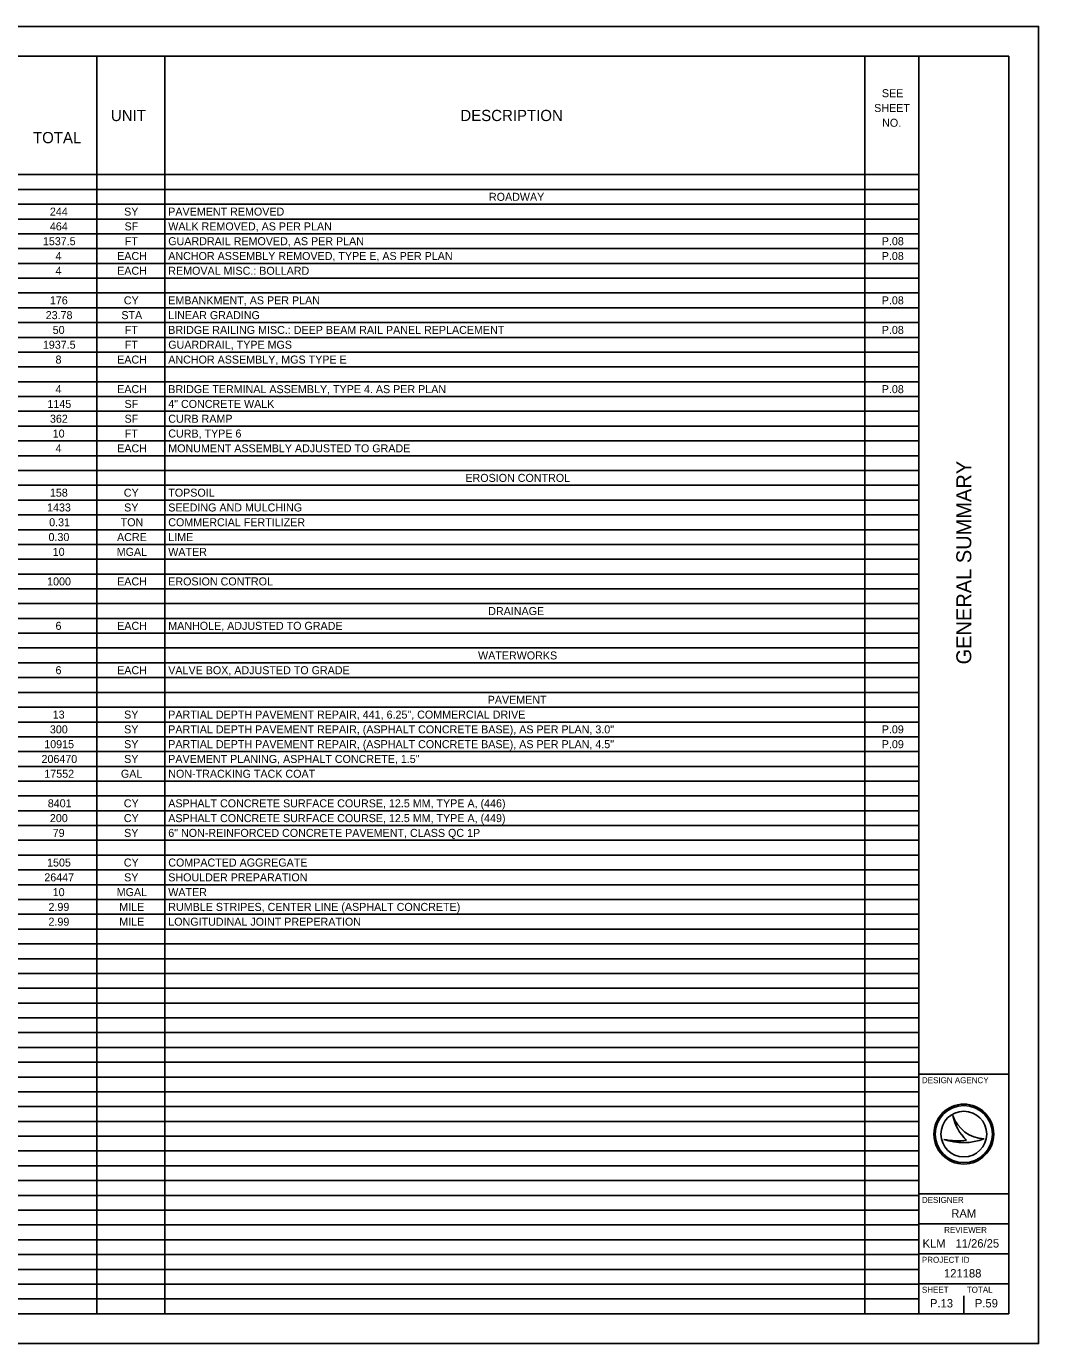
# Model space of a CAD drawing. Extents: x 0 to 34, y 0 to 22.
# Drawn here: x 17.09 to 34, y 0 to 22 of the extents above; entities that cross this region are included whole.
import ezdxf

# ---------------------------------------------------------------- set-up
doc = ezdxf.new("R2010")
doc.units = 0
for name, color, linetype in [('Default', 7, 'Continuous'), ('SH_Border', 7, 'Continuous'), ('SH_Cut_Line', 7, 'Continuous'), ('SH_Data', 7, 'Continuous')]:
    doc.layers.add(name, color=color, linetype=linetype)

msp = doc.modelspace()

# ---------------------------------------------------------------- linework, layer by layer
at = {"layer": 'Default'}
for p, q in [((1.5, 21.5), (32, 21.5)), ((18.27, 21.5), (18.27, 0.5)), ((19.404, 21.5), (19.404, 0.5)), ((31.098, 21.5), (31.098, 0.5)), ((32, 21.5), (32, 0.5)), ((1.5, 19.524), (32, 19.524)), ((1.5, 19.276), (32, 19.276)), ((1.5, 19.029), (32, 19.029)), ((1.5, 18.782), (32, 18.782)), ((1.5, 18.535), (32, 18.535)), ((1.5, 18.288), (32, 18.288)), ((1.5, 18.041), (32, 18.041)), ((1.5, 17.794), (32, 17.794)), ((1.5, 17.547), (32, 17.547)), ((1.5, 17.3), (32, 17.3)), ((1.5, 17.053), (32, 17.053)), ((1.5, 16.806), (32, 16.806)), ((1.5, 16.559), (32, 16.559)), ((1.5, 16.312), (32, 16.312)), ((1.5, 16.065), (32, 16.065)), ((1.5, 15.818), (32, 15.818)), ((1.5, 15.571), (32, 15.571)), ((1.5, 15.324), (32, 15.324)), ((1.5, 15.076), (32, 15.076)), ((1.5, 14.829), (32, 14.829)), ((1.5, 14.582), (32, 14.582)), ((1.5, 14.335), (32, 14.335)), ((1.5, 14.088), (32, 14.088)), ((1.5, 13.841), (32, 13.841)), ((1.5, 13.594), (32, 13.594)), ((1.5, 13.347), (32, 13.347)), ((1.5, 13.1), (32, 13.1)), ((1.5, 12.853), (32, 12.853)), ((1.5, 12.606), (32, 12.606)), ((1.5, 12.359), (32, 12.359)), ((1.5, 12.112), (32, 12.112)), ((1.5, 11.865), (32, 11.865)), ((1.5, 11.618), (32, 11.618)), ((1.5, 11.371), (32, 11.371)), ((1.5, 11.124), (32, 11.124)), ((1.5, 10.876), (32, 10.876)), ((1.5, 10.629), (32, 10.629)), ((1.5, 10.382), (32, 10.382)), ((1.5, 10.135), (32, 10.135)), ((1.5, 9.888), (32, 9.888)), ((1.5, 9.641), (32, 9.641)), ((1.5, 9.394), (32, 9.394)), ((1.5, 9.147), (32, 9.147)), ((1.5, 8.9), (32, 8.9)), ((1.5, 8.653), (32, 8.653)), ((1.5, 8.406), (32, 8.406)), ((1.5, 8.159), (32, 8.159)), ((1.5, 7.912), (32, 7.912)), ((1.5, 7.665), (32, 7.665)), ((1.5, 7.418), (32, 7.418)), ((1.5, 7.171), (32, 7.171)), ((1.5, 6.924), (32, 6.924)), ((1.5, 6.676), (32, 6.676)), ((1.5, 6.429), (32, 6.429)), ((1.5, 6.182), (32, 6.182)), ((1.5, 5.935), (32, 5.935)), ((1.5, 5.688), (32, 5.688)), ((1.5, 5.441), (32, 5.441)), ((1.5, 5.194), (32, 5.194)), ((1.5, 4.947), (32, 4.947)), ((1.5, 4.7), (32, 4.7)), ((1.5, 4.453), (32, 4.453)), ((1.5, 4.206), (32, 4.206)), ((1.5, 3.959), (32, 3.959)), ((1.5, 3.712), (32, 3.712)), ((1.5, 3.465), (32, 3.465)), ((1.5, 3.218), (32, 3.218)), ((1.5, 2.971), (32, 2.971)), ((1.5, 2.724), (32, 2.724)), ((1.5, 2.476), (32, 2.476)), ((1.5, 2.229), (32, 2.229)), ((1.5, 1.982), (32, 1.982)), ((1.5, 1.735), (32, 1.735)), ((1.5, 1.488), (32, 1.488)), ((1.5, 1.241), (32, 1.241)), ((1.5, 0.994), (32, 0.994)), ((1.5, 0.747), (32, 0.747)), ((1.5, 0.5), (32, 0.5))]:
    msp.add_line(p, q, dxfattribs=at)
for points in [[(19.404, 12.359), (31.098, 12.359), (31.098, 12.112), (19.404, 12.112)], [(19.404, 11.618), (31.098, 11.618), (31.098, 11.371), (19.404, 11.371)], [(19.404, 10.876), (31.098, 10.876), (31.098, 10.629), (19.404, 10.629)], [(19.404, 10.629), (31.098, 10.629), (31.098, 10.382), (19.404, 10.382)], [(19.404, 10.382), (31.098, 10.382), (31.098, 10.135), (19.404, 10.135)], [(19.404, 10.135), (31.098, 10.135), (31.098, 9.888), (19.404, 9.888)]]:
    msp.add_lwpolyline(points, close=True, dxfattribs=at)
at = {"layer": 'SH_Border'}
for p, q in [((32, 0.5), (32, 21.5)), ((32, 4.5), (33.5, 4.5)), ((32, 2.5), (33.5, 2.5)), ((32, 2), (33.5, 2)), ((32, 1.5), (33.5, 1.5)), ((32, 1), (33.5, 1))]:
    msp.add_line(p, q, dxfattribs=at)
msp.add_lwpolyline([(1.5, 21.5), (33.5, 21.5), (33.5, 0.5), (1.5, 0.5)], close=True, dxfattribs=at)
at = {"layer": 'SH_Cut_Line'}
msp.add_lwpolyline([(0, 0), (34, 0), (34, 22), (0, 22)], close=True, dxfattribs=at)
at = {"layer": 'SH_Data'}
for p, q in [((32.567, 3.81), (32.567, 3.81)), ((32.417, 3.41), (32.417, 3.41)), ((32.75, 3.5), (32.75, 3.5)), ((33.087, 3.419), (33.087, 3.419)), ((32.375, 0.675), (32.375, 0.675)), ((32.75, 0.5), (32.75, 0.8))]:
    msp.add_line(p, q, dxfattribs=at)
for radius in [0.5, 0.477, 0.477, 0.382]:
    msp.add_circle((32.75, 3.5), radius, dxfattribs=at)
for centre, radius, start, end in [((33.116, 3.998), 0.58, 198.9257, 198.9319), ((33.347, 3.97), 0.796, 191.6379, 191.6421), ((33.116, 3.998), 0.58, 198.9319, 267.1657), ((33.347, 3.97), 0.796, 191.6421, 226.0947), ((32.739, 4.37), 1.013, 251.4576, 290.0832), ((32.648, 4.654), 1.266, 259.4964, 259.4995), ((32.739, 4.37), 1.013, 251.4527, 251.4576), ((32.648, 4.654), 1.266, 259.4995, 276.6672)]:
    msp.add_arc(centre, radius, start, end, dxfattribs=at)

# ---------------------------------------------------------------- texts
at = {"layer": 'Default'}
for s, height, p in [('SEE', 0.1337, (31.382, 20.817)), ('SHEET', 0.1337, (31.253, 20.57)), ('UNIT', 0.1872, (18.505, 20.418)), ('DESCRIPTION', 0.18718, (24.342, 20.418)), ('NO.', 0.1337, (31.386, 20.323)), ('TOTAL', 0.1872, (17.204, 20.048)), ('ROADWAY', 0.1337, (24.819, 19.086)), ('244', 0.1337, (17.486, 18.839)), ('SY', 0.1337, (18.726, 18.839)), ('PAVEMENT REMOVED', 0.1337, (19.463, 18.839)), ('464', 0.1337, (17.486, 18.592)), ('SF', 0.1337, (18.733, 18.592)), ('WALK REMOVED, AS PER PLAN', 0.1337, (19.463, 18.592)), ('1537.5', 0.1337, (17.369, 18.345)), ('GUARDRAIL REMOVED, AS PER PLAN', 0.1337, (19.463, 18.345)), ('P.08', 0.1337, (31.38, 18.345)), ('FT', 0.1337, (18.736, 18.345)), ('4', 0.134, (17.58, 18.098)), ('EACH', 0.1337, (18.61, 18.098)), ('ANCHOR ASSEMBLY REMOVED, TYPE E, AS PER PLAN', 0.1337, (19.463, 18.098)), ('P.08', 0.1337, (31.38, 18.098)), ('4', 0.134, (17.58, 17.851)), ('EACH', 0.1337, (18.61, 17.851)), ('REMOVAL MISC.: BOLLARD', 0.1337, (19.463, 17.851)), ('176', 0.1337, (17.486, 17.357)), ('CY', 0.1337, (18.721, 17.357)), ('EMBANKMENT, AS PER PLAN', 0.1337, (19.463, 17.357)), ('P.08', 0.1337, (31.38, 17.357)), ('23.78', 0.1337, (17.416, 17.11)), ('STA', 0.1337, (18.68, 17.11)), ('LINEAR GRADING', 0.1337, (19.463, 17.11)), ('50', 0.1337, (17.533, 16.863)), ('FT', 0.1337, (18.736, 16.863)), ('BRIDGE RAILING MISC.: DEEP BEAM RAIL PANEL REPLACEMENT', 0.1337, (19.463, 16.863)), ('P.08', 0.1337, (31.38, 16.863)), ('1937.5', 0.1337, (17.369, 16.616)), ('FT', 0.1337, (18.736, 16.616)), ('GUARDRAIL, TYPE MGS', 0.1337, (19.463, 16.616)), ('8', 0.134, (17.58, 16.368)), ('EACH', 0.1337, (18.61, 16.368)), ('ANCHOR ASSEMBLY, MGS TYPE E', 0.1337, (19.463, 16.368)), ('4', 0.134, (17.58, 15.874)), ('EACH', 0.1337, (18.61, 15.874)), ('BRIDGE TERMINAL ASSEMBLY, TYPE 4. AS PER PLAN', 0.1337, (19.463, 15.874)), ('P.08', 0.1337, (31.38, 15.874)), ('1145', 0.1337, (17.445, 15.627)), ('SF', 0.1337, (18.733, 15.627)), ('4" CONCRETE WALK', 0.1337, (19.463, 15.627)), ('362', 0.1337, (17.487, 15.38)), ('SF', 0.1337, (18.733, 15.38)), ('CURB RAMP', 0.1337, (19.463, 15.38)), ('10', 0.1337, (17.533, 15.133)), ('FT', 0.1337, (18.736, 15.133)), ('CURB, TYPE 6', 0.1337, (19.463, 15.133)), ('4', 0.134, (17.58, 14.886)), ('EACH', 0.1337, (18.61, 14.886)), ('MONUMENT ASSEMBLY ADJUSTED TO GRADE', 0.1337, (19.463, 14.886)), ('EROSION CONTROL', 0.1337, (24.426, 14.392)), ('158', 0.1337, (17.486, 14.145)), ('CY', 0.1337, (18.721, 14.145)), ('TOPSOIL', 0.1337, (19.463, 14.145)), ('1433', 0.1337, (17.439, 13.898)), ('SY', 0.1337, (18.726, 13.898)), ('SEEDING AND MULCHING', 0.1337, (19.463, 13.898)), ('0.31', 0.1337, (17.474, 13.651)), ('TON', 0.1337, (18.668, 13.651)), ('COMMERCIAL FERTILIZER', 0.1337, (19.463, 13.651)), ('0.30', 0.1337, (17.463, 13.404)), ('ACRE', 0.1337, (18.608, 13.404)), ('LIME', 0.1337, (19.463, 13.404)), ('10', 0.1337, (17.533, 13.157)), ('MGAL', 0.1337, (18.602, 13.157)), ('WATER', 0.1337, (19.463, 13.157)), ('1000', 0.1337, (17.44, 12.663)), ('EACH', 0.1337, (18.61, 12.663)), ('EROSION CONTROL', 0.1337, (19.463, 12.663)), ('DRAINAGE', 0.1337, (24.807, 12.168)), ('6', 0.134, (17.58, 11.921)), ('EACH', 0.1337, (18.61, 11.921)), ('MANHOLE, ADJUSTED TO GRADE', 0.1337, (19.463, 11.921)), ('WATERWORKS', 0.1337, (24.637, 11.427)), ('6', 0.134, (17.58, 11.18)), ('EACH', 0.1337, (18.61, 11.18)), ('VALVE BOX, ADJUSTED TO GRADE', 0.1337, (19.463, 11.18)), ('PAVEMENT', 0.1337, (24.798, 10.686)), ('13', 0.1337, (17.533, 10.439)), ('SY', 0.1337, (18.726, 10.439)), ('PARTIAL DEPTH PAVEMENT REPAIR, 441, 6.25", COMMERCIAL DRIVE', 0.1337, (19.463, 10.439)), ('300', 0.1337, (17.486, 10.192)), ('SY', 0.1337, (18.726, 10.192)), ('PARTIAL DEPTH PAVEMENT REPAIR, (ASPHALT CONCRETE BASE), AS PER PLAN, 3.0"', 0.1337, (19.463, 10.192)), ('P.09', 0.1337, (31.38, 10.192)), ('10915', 0.1337, (17.392, 9.945)), ('SY', 0.1337, (18.726, 9.945)), ('PARTIAL DEPTH PAVEMENT REPAIR, (ASPHALT CONCRETE BASE), AS PER PLAN, 4.5"', 0.1337, (19.463, 9.945)), ('P.09', 0.1337, (31.38, 9.945)), ('206470', 0.1337, (17.346, 9.698)), ('SY', 0.1337, (18.726, 9.698)), ('PAVEMENT PLANING, ASPHALT CONCRETE, 1.5"', 0.1337, (19.463, 9.698)), ('17552', 0.1337, (17.393, 9.451)), ('GAL', 0.1337, (18.672, 9.451)), ('NON-TRACKING TACK COAT', 0.1337, (19.463, 9.451)), ('8401', 0.1337, (17.451, 8.957)), ('CY', 0.1337, (18.721, 8.957)), ('ASPHALT CONCRETE SURFACE COURSE, 12.5 MM, TYPE A, (446)', 0.1337, (19.463, 8.957)), ('200', 0.1337, (17.486, 8.71)), ('CY', 0.1337, (18.721, 8.71)), ('ASPHALT CONCRETE SURFACE COURSE, 12.5 MM, TYPE A, (449)', 0.1337, (19.463, 8.71)), ('79', 0.1337, (17.533, 8.463)), ('SY', 0.1337, (18.726, 8.463)), ('6" NON-REINFORCED CONCRETE PAVEMENT, CLASS QC 1P', 0.1337, (19.463, 8.463)), ('1505', 0.1337, (17.439, 7.968)), ('CY', 0.1337, (18.721, 7.968)), ('COMPACTED AGGREGATE', 0.1337, (19.463, 7.968)), ('26447', 0.1337, (17.393, 7.721)), ('SY', 0.1337, (18.726, 7.721)), ('SHOULDER PREPARATION', 0.1337, (19.463, 7.721)), ('10', 0.1337, (17.533, 7.474)), ('MGAL', 0.1337, (18.602, 7.474)), ('WATER', 0.1337, (19.463, 7.474)), ('2.99', 0.1337, (17.463, 7.227)), ('MILE', 0.1337, (18.645, 7.227)), ('RUMBLE STRIPES, CENTER LINE (ASPHALT CONCRETE)', 0.1337, (19.463, 7.227)), ('2.99', 0.1337, (17.463, 6.98)), ('MILE', 0.1337, (18.645, 6.98)), ('LONGITUDINAL JOINT PREPERATION', 0.1337, (19.463, 6.98))]:
    msp.add_text(s, height=height, dxfattribs=at).set_placement(p)
at = {"layer": 'SH_Data'}
msp.add_text('GENERAL SUMMARY', height=0.25, rotation=90, dxfattribs=at).set_placement((32.875, 11.344))
for s, height, p in [('DESIGN AGENCY', 0.1, (32.05, 4.35)), ('DESIGNER', 0.1, (32.05, 2.35)), ('RAM', 0.14, (32.541, 2.105)), ('REVIEWER', 0.1, (32.422, 1.85)), ('KLM', 0.14, (32.061, 1.605)), ('11/26/25', 0.14, (32.611, 1.605)), ('PROJECT ID', 0.1, (32.05, 1.35)), ('121188', 0.14, (32.419, 1.105)), ('SHEET', 0.1, (32.05, 0.85)), ('TOTAL', 0.1, (32.8, 0.85)), ('P.13', 0.14, (32.185, 0.605)), ('P.59', 0.14, (32.934, 0.605))]:
    msp.add_text(s, height=height, dxfattribs=at).set_placement(p)

doc.saveas('drawing.dxf')
